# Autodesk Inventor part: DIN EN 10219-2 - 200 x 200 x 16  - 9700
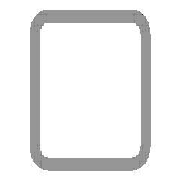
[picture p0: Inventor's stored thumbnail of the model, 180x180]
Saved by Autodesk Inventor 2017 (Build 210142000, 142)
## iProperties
IsCustomPart: 1
Created: 2017-11
Part Number: DIN EN 10219-2 - 200 x 200 x 16  - 9700
Material: Steel, Mild
Description: Cold formed welded structural hollow sections of non-alloy and fine grain structural steel
Document SubType Name: Modeling
Standard: DIN
Designer: iusti
Standard Revision: 2006-07
Standards Organization: DIN
Language: en-US
Size Designation: 200 x 200 x 16
Categories: <MemberInstance><Categories><Category DisplayName="Structural Shapes" InternalName="089c4875-fa83-4c05-b084-43b9cc11f5ed" Mnemonic="GRDR"><CategoryParameter Dis
Stock Number: 200 x 200 x 16
Density: 7.85 g/cm^3
Appearance: Semi-Polished
Mass: 796255 g
Surface Area: 127094 cm^2
Volume: 101434 cm^3
_CCFamilyMember: 103
_CCFamilyDisplayName: DIN EN 10219-2 (Square Hollow Section - Cold Formed) - Cold formed welded structural hollow sections of non-alloy and fine grain structural steel
_FrameMemberDoc: Frame Member File
_Version: 15.0.0
_GetPNFromCC: 1
G_L: 9700.000 mm
G_W: 200.000 mm
G_H: 200.000 mm
+B9E1DA22-D309-4BBF-9627-4CE74C33B13E+CUTDETAIL1: Cut
+2FA9747E-09CC-4283-B5AE-DE9A0485B1EC+CUTDETAIL2: Cut
+00569EB8-A9A7-487F-AD20-8A8F135713C5+CUTDETAIL3: Miter 45.00 deg
+1BFDA885-F50F-46B1-BDA8-57B8AE23BE4C+CUTDETAIL4: Miter 45.00 deg
Author: iusti
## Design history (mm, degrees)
node "Start plane"
node "End plane"
sketch "Sketch"
  geometry: L1 (-100, -52)-(-100, 52); L2 (-52, 100)-(52, 100); L3 (100, 52)-(100, -52); L4 (52, -100)-(-52, -100); L5 (-52, 84)-(52, 84); L6 (84, 52)-(84, -52); L7 (52, -84)-(-52, -84); L8 (-84, -52)-(-84, 52); L9 (0, 153.918)-(0, -153.918) reference; L10 (-153.918, 0)-(153.918, 0) reference; A1 r 48 centre (-52, -52) between (-100, -52) and (-52, -100); A2 r 48 centre (-52, 52) between (-52, 100) and (-100, 52); A3 r 48 centre (52, 52) between (100, 52) and (52, 100); A4 r 48 centre (52, -52) between (52, -100) and (100, -52); A5 r 32 centre (-52, 52) between (-52, 84) and (-84, 52); A6 r 32 centre (52, 52) between (84, 52) and (52, 84); A7 r 32 centre (52, -52) between (52, -84) and (84, -52); A8 r 32 centre (-52, -52) between (-84, -52) and (-52, -84)
  constraints: 16 end point, 16 point on circle, 8 centre point, 8 tangent, 4 parallel, 3 equal radius, 2 perpendicular, 7 other
  dimensions: "d7" = 48 radius of A1 (= G_IR); "d10" = 200 distance between parallel lines of L2 L4 (= G_H); "d11" = 200 distance between parallel lines of L1 L3 (= G_W); "d12" = 16 distance between parallel lines of L3 L6 (= G_T); "d15" = 100 distance between parallel lines of L2 L10 (= 0.5 x d10); "d16" = 100 distance between parallel lines of L9 L3 (= 0.5 x d11)
extrude "Body" new body sketch "Sketch" stored distance "d3" = 9700 (= G_L); taper "d4" = 0 deg
node "Driven Length"
  sketch "Sketch3"
    geometry: L1 (0, 0)-(10, 0) reference
    constraints: 2 end point, 1 horizontal
  workplane "Work Plane3"
  sketch "Sketch4"
    geometry: L1 (-2, -100)-(12, -100) reference; L2 (-2, 9600)-(12, 9600) reference
    dimensions: "d18" = 9700 distance between parallel lines of L1 L2 (derived)
workplane "Work Plane4"
split "Split1"
workplane "Work Plane5"
split "Split2"
workplane "Work Plane6"
split "Split3"
workplane "Work Plane7"
split "Split4"
body "Solid1"
other parameters: "G_W" = 200 [user parameter; used in 1 equation term], "G_H" = 200 [user parameter; used in 1 equation term], "G_T" = 16 [user parameter; used in 1 equation term], "G_IR" = 48 [user parameter; used in 1 equation term], "G_L" = 9700 (= d18) [user parameter; used in 1 equation term], "d17" = 90 deg
